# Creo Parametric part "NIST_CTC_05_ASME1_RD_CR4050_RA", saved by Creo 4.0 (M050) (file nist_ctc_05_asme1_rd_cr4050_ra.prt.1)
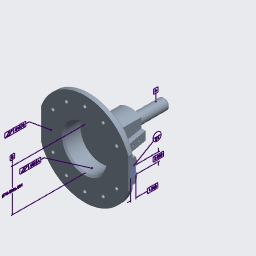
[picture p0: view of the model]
Units: Inch lbm Second (Pro/E Default); INCH, POUND, SECS

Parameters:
  PART_NUMBER = "NIST PMI CTC 05 ASME1"
  REVISION = "D"
  DESCRIPTION = "NIST PMI test model downloaded from http://go.usa.gov/mGVm"
  SCREW_SIZE = "1/2-13"
  METRIC = "NO"

Other parameters: DRILL_POINT_ANGLE, DRILL_DEPTH, DRILL_DIAMETER, CBORE_DEPTH, PITCH, THREAD_DIAMETER, THREADS_PER_INCH, THREAD_DEPTH

Created from: NIST_CTC_05_ASME1_CR2040_RD.PRT

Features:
  1. datum plane "RIGHT"
  2. datum plane "TOP"
  3. datum plane "FRONT"
  4. coordinate system
  5. curve
  6. protrusion
  7. curve
  8. protrusion
  9. curve
  10. protrusion
  11. curve
  12. cut
  13. curve
  14. pattern
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
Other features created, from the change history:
  imported feature "Curve From File id 5869"
  sketch "Sketch 15"
  extruded cut "Extrude 9"

Other named items: DATUM_TAG_A, AD391, DATUM_TAG_B, GP16, DRF1, GP17, DRF2, AD394, AD397, DT4, AD400, AD403, DT5, DATUM_TAG_C, DATUM_TAG_D, GP18, DRF3, GP19, GP20, AD405, GP21, GP22, GP23, GP24, DRF4, GP25, DRF5, MBD_A, MBD_B, ANNOT_LAYER_STATE0013, ANNOT_LAYER_STATE0014, DEFAULT_LAYER_STATE

Layers: ALL_ANNOTATIONS, ALL_AXES, ALL_CSYS, ALL_CURVES, ALL_PLANES, ALL_POINTS, ALL_QUILTS, DEF_CSYS, DEF_PLANES, MBD_A, MBD_B

Notes:  l| .010 | D | �⌰ | .002 | A

Family table entries: GENERIC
